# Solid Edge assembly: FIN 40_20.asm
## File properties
Title: Zylinder
Author: bmolnar
Template: iso assembly.asm
Last saved by: bmolnar
Revision: 10
Application: Solid Edge
Username: bmolnar
Dokumentum tartalom típus: 1
Document Number: FIN 40/20
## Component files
Kit_1.par
Profilrohr.par
Kit_2.par
Kolbenstange.par
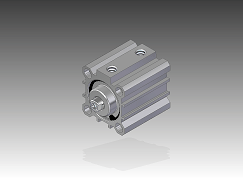
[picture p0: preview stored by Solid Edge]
